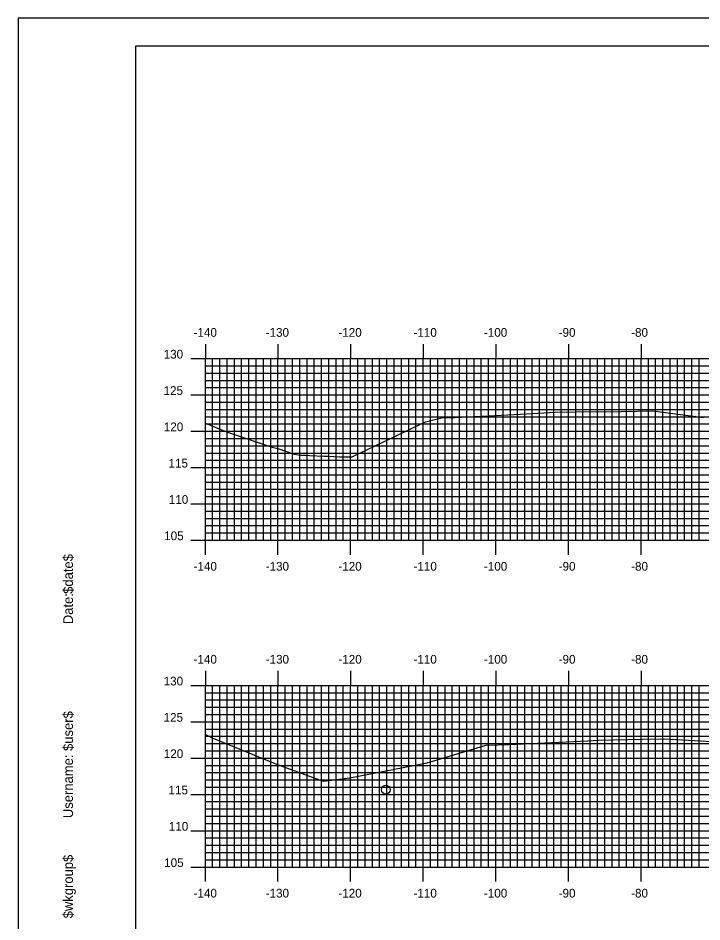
# Model space of a CAD drawing. Extents: x 853894 to 854237, y 366605 to 366825.
# Drawn here: x 853893.7 to 853987.9, y 366700.5 to 366824.9 of the extents above; entities that cross this region are included whole.
import ezdxf

# ---------------------------------------------------------------- set-up
doc = ezdxf.new("R2010")
doc.units = 0
for name, color, linetype in [('BORDER', 7, 'Continuous'), ('H_V ANNOTATION', 7, 'Continuous'), ('M_Roadway_Centerline', 7, 'Continuous'), ('MAJOR', 7, 'Continuous'), ('MINOR', 7, 'Continuous'), ('PLOT BOUNDARY', 7, 'Continuous'), ('S_Drainage_Invert', 7, 'Continuous'), ('S_Roadway_Centerline', 7, 'Continuous')]:
    doc.layers.add(name, color=color, linetype=linetype)

msp = doc.modelspace()

# ---------------------------------------------------------------- linework, layer by layer
at = {"layer": 'BORDER'}
msp.add_lwpolyline([(853909.93, 366611.06), (854229.93, 366611.06), (854229.93, 366821.06), (853909.93, 366821.06)], close=True, dxfattribs=at)
at = {"layer": 'MAJOR'}
for p, q in [((853919.53, 366780.06), (853919.53, 366778.06)), ((853929.53, 366780.06), (853929.53, 366778.06)), ((853939.53, 366780.06), (853939.53, 366778.06)), ((853949.53, 366780.06), (853949.53, 366778.06)), ((853959.53, 366780.06), (853959.53, 366778.06)), ((853969.53, 366780.06), (853969.53, 366778.06)), ((853979.53, 366780.06), (853979.53, 366778.06)), ((853917.53, 366778.06), (853919.53, 366778.06)), ((853919.53, 366778.06), (854199.53, 366778.06)), ((853919.53, 366753.06), (853919.53, 366778.06)), ((853919.53, 366753.06), (853919.53, 366778.06)), ((853919.53, 366778.06), (854199.53, 366778.06)), ((853929.53, 366753.06), (853929.53, 366778.06)), ((853939.53, 366753.06), (853939.53, 366778.06)), ((853949.53, 366753.06), (853949.53, 366778.06)), ((853959.53, 366753.06), (853959.53, 366778.06)), ((853969.53, 366753.06), (853969.53, 366778.06)), ((853979.53, 366753.06), (853979.53, 366778.06)), ((853917.53, 366773.06), (853919.53, 366773.06)), ((853919.53, 366773.06), (854199.53, 366773.06)), ((853917.53, 366768.06), (853919.53, 366768.06)), ((853919.53, 366768.06), (854199.53, 366768.06)), ((853917.53, 366763.06), (853919.53, 366763.06)), ((853919.53, 366763.06), (854199.53, 366763.06)), ((853917.53, 366758.06), (853919.53, 366758.06)), ((853919.53, 366758.06), (854199.53, 366758.06)), ((853917.53, 366753.06), (853919.53, 366753.06)), ((853919.53, 366753.06), (854199.53, 366753.06)), ((853919.53, 366753.06), (854199.53, 366753.06)), ((853919.53, 366751.05), (853919.53, 366753.06)), ((853929.53, 366751.05), (853929.53, 366753.06)), ((853939.53, 366751.05), (853939.53, 366753.06)), ((853949.53, 366751.05), (853949.53, 366753.06)), ((853959.53, 366751.05), (853959.53, 366753.06)), ((853969.53, 366751.05), (853969.53, 366753.06)), ((853979.53, 366751.05), (853979.53, 366753.06)), ((853919.53, 366735.06), (853919.53, 366733.06)), ((853929.53, 366735.06), (853929.53, 366733.06)), ((853939.53, 366735.06), (853939.53, 366733.06)), ((853949.53, 366735.06), (853949.53, 366733.06)), ((853959.53, 366735.06), (853959.53, 366733.06)), ((853969.53, 366735.06), (853969.53, 366733.06)), ((853979.53, 366735.06), (853979.53, 366733.06)), ((853917.53, 366733.06), (853919.53, 366733.06)), ((853919.53, 366733.06), (854199.53, 366733.06)), ((853919.53, 366708.06), (853919.53, 366733.06)), ((853919.53, 366708.06), (853919.53, 366733.06)), ((853919.53, 366733.06), (854199.53, 366733.06)), ((853929.53, 366708.06), (853929.53, 366733.06)), ((853939.53, 366708.06), (853939.53, 366733.06)), ((853949.53, 366708.06), (853949.53, 366733.06)), ((853959.53, 366708.06), (853959.53, 366733.06)), ((853969.53, 366708.06), (853969.53, 366733.06)), ((853979.53, 366708.06), (853979.53, 366733.06)), ((853917.53, 366728.06), (853919.53, 366728.06)), ((853919.53, 366728.06), (854199.53, 366728.06)), ((853917.53, 366723.06), (853919.53, 366723.06)), ((853919.53, 366723.06), (854199.53, 366723.06)), ((853917.53, 366718.06), (853919.53, 366718.06)), ((853919.53, 366718.06), (854199.53, 366718.06)), ((853917.53, 366713.06), (853919.53, 366713.06)), ((853919.53, 366713.06), (854199.53, 366713.06)), ((853917.53, 366708.06), (853919.53, 366708.06)), ((853919.53, 366708.06), (854199.53, 366708.06)), ((853919.53, 366708.06), (854199.53, 366708.06)), ((853919.53, 366706.05), (853919.53, 366708.06)), ((853929.53, 366706.05), (853929.53, 366708.06)), ((853939.53, 366706.05), (853939.53, 366708.06)), ((853949.53, 366706.05), (853949.53, 366708.06)), ((853959.53, 366706.05), (853959.53, 366708.06)), ((853969.53, 366706.05), (853969.53, 366708.06)), ((853979.53, 366706.05), (853979.53, 366708.06))]:
    msp.add_line(p, q, dxfattribs=at)
at = {"layer": 'MINOR'}
for p, q in [((853919.53, 366753.06), (853919.53, 366778.06)), ((853920.53, 366753.06), (853920.53, 366778.06)), ((853921.53, 366753.06), (853921.53, 366778.06)), ((853922.53, 366753.06), (853922.53, 366778.06)), ((853923.53, 366753.06), (853923.53, 366778.06)), ((853924.53, 366753.06), (853924.53, 366778.06)), ((853925.53, 366753.06), (853925.53, 366778.06)), ((853926.53, 366753.06), (853926.53, 366778.06)), ((853927.53, 366753.06), (853927.53, 366778.06)), ((853928.53, 366753.06), (853928.53, 366778.06)), ((853930.53, 366753.06), (853930.53, 366778.06)), ((853931.53, 366753.06), (853931.53, 366778.06)), ((853932.53, 366753.06), (853932.53, 366778.06)), ((853933.53, 366753.06), (853933.53, 366778.06)), ((853934.53, 366753.06), (853934.53, 366778.06)), ((853935.53, 366753.06), (853935.53, 366778.06)), ((853936.53, 366753.06), (853936.53, 366778.06)), ((853937.53, 366753.06), (853937.53, 366778.06)), ((853938.53, 366753.06), (853938.53, 366778.06)), ((853940.53, 366753.06), (853940.53, 366778.06)), ((853941.53, 366753.06), (853941.53, 366778.06)), ((853942.53, 366753.06), (853942.53, 366778.06)), ((853943.53, 366753.06), (853943.53, 366778.06)), ((853944.53, 366753.06), (853944.53, 366778.06)), ((853945.53, 366753.06), (853945.53, 366778.06)), ((853946.53, 366753.06), (853946.53, 366778.06)), ((853947.53, 366753.06), (853947.53, 366778.06)), ((853948.53, 366753.06), (853948.53, 366778.06)), ((853950.53, 366753.06), (853950.53, 366778.06)), ((853951.53, 366753.06), (853951.53, 366778.06)), ((853952.53, 366753.06), (853952.53, 366778.06)), ((853953.53, 366753.06), (853953.53, 366778.06)), ((853954.53, 366753.06), (853954.53, 366778.06)), ((853955.53, 366753.06), (853955.53, 366778.06)), ((853956.53, 366753.06), (853956.53, 366778.06)), ((853957.53, 366753.06), (853957.53, 366778.06)), ((853958.53, 366753.06), (853958.53, 366778.06)), ((853960.53, 366753.06), (853960.53, 366778.06)), ((853961.53, 366753.06), (853961.53, 366778.06)), ((853962.53, 366753.06), (853962.53, 366778.06)), ((853963.53, 366753.06), (853963.53, 366778.06)), ((853964.53, 366753.06), (853964.53, 366778.06)), ((853965.53, 366753.06), (853965.53, 366778.06)), ((853966.53, 366753.06), (853966.53, 366778.06)), ((853967.53, 366753.06), (853967.53, 366778.06)), ((853968.53, 366753.06), (853968.53, 366778.06)), ((853970.53, 366753.06), (853970.53, 366778.06)), ((853971.53, 366753.06), (853971.53, 366778.06)), ((853972.53, 366753.06), (853972.53, 366778.06)), ((853973.53, 366753.06), (853973.53, 366778.06)), ((853974.53, 366753.06), (853974.53, 366778.06)), ((853975.53, 366753.06), (853975.53, 366778.06)), ((853976.53, 366753.06), (853976.53, 366778.06)), ((853977.53, 366753.06), (853977.53, 366778.06)), ((853978.53, 366753.06), (853978.53, 366778.06)), ((853980.53, 366753.06), (853980.53, 366778.06)), ((853981.53, 366753.06), (853981.53, 366778.06)), ((853982.53, 366753.06), (853982.53, 366778.06)), ((853983.53, 366753.06), (853983.53, 366778.06)), ((853984.53, 366753.06), (853984.53, 366778.06)), ((853985.53, 366753.06), (853985.53, 366778.06)), ((853986.53, 366753.06), (853986.53, 366778.06)), ((853987.53, 366753.06), (853987.53, 366778.06)), ((853919.53, 366777.06), (854199.53, 366777.06)), ((853919.53, 366777.06), (853921.53, 366777.06)), ((853919.53, 366776.06), (854199.53, 366776.06)), ((853919.53, 366776.06), (853921.53, 366776.06)), ((853919.53, 366775.06), (854199.53, 366775.06)), ((853919.53, 366775.06), (853921.53, 366775.06)), ((853919.53, 366774.06), (854199.53, 366774.06)), ((853919.53, 366774.06), (853921.53, 366774.06)), ((853919.53, 366772.06), (854199.53, 366772.06)), ((853919.53, 366772.06), (853921.53, 366772.06)), ((853919.53, 366771.06), (854199.53, 366771.06)), ((853919.53, 366771.06), (853921.53, 366771.06)), ((853919.53, 366770.06), (854199.53, 366770.06)), ((853919.53, 366770.06), (853921.53, 366770.06)), ((853919.53, 366769.06), (854199.53, 366769.06)), ((853919.53, 366769.06), (853921.53, 366769.06)), ((853919.53, 366767.06), (854199.53, 366767.06)), ((853919.53, 366767.06), (853921.53, 366767.06)), ((853919.53, 366766.06), (854199.53, 366766.06)), ((853919.53, 366766.06), (853921.53, 366766.06)), ((853919.53, 366765.06), (854199.53, 366765.06)), ((853919.53, 366765.06), (853921.53, 366765.06)), ((853919.53, 366764.06), (854199.53, 366764.06)), ((853919.53, 366764.06), (853921.53, 366764.06)), ((853919.53, 366762.06), (854199.53, 366762.06)), ((853919.53, 366762.06), (853921.53, 366762.06)), ((853919.53, 366761.06), (854199.53, 366761.06)), ((853919.53, 366761.06), (853921.53, 366761.06)), ((853919.53, 366760.06), (854199.53, 366760.06)), ((853919.53, 366760.06), (853921.53, 366760.06)), ((853919.53, 366759.06), (854199.53, 366759.06)), ((853919.53, 366759.06), (853921.53, 366759.06)), ((853919.53, 366757.06), (854199.53, 366757.06)), ((853919.53, 366757.06), (853921.53, 366757.06)), ((853919.53, 366756.06), (854199.53, 366756.06)), ((853919.53, 366756.06), (853921.53, 366756.06)), ((853919.53, 366755.06), (854199.53, 366755.06)), ((853919.53, 366755.06), (853921.53, 366755.06)), ((853919.53, 366754.06), (854199.53, 366754.06)), ((853919.53, 366754.06), (853921.53, 366754.06)), ((853920.53, 366708.06), (853920.53, 366733.06)), ((853921.53, 366708.06), (853921.53, 366733.06)), ((853922.53, 366708.06), (853922.53, 366733.06)), ((853923.53, 366708.06), (853923.53, 366733.06)), ((853924.53, 366708.06), (853924.53, 366733.06)), ((853925.53, 366708.06), (853925.53, 366733.06)), ((853926.53, 366708.06), (853926.53, 366733.06)), ((853927.53, 366708.06), (853927.53, 366733.06)), ((853928.53, 366708.06), (853928.53, 366733.06)), ((853930.53, 366708.06), (853930.53, 366733.06)), ((853931.53, 366708.06), (853931.53, 366733.06)), ((853932.53, 366708.06), (853932.53, 366733.06)), ((853933.53, 366708.06), (853933.53, 366733.06)), ((853934.53, 366708.06), (853934.53, 366733.06)), ((853935.53, 366708.06), (853935.53, 366733.06)), ((853936.53, 366708.06), (853936.53, 366733.06)), ((853937.53, 366708.06), (853937.53, 366733.06)), ((853938.53, 366708.06), (853938.53, 366733.06)), ((853940.53, 366708.06), (853940.53, 366733.06)), ((853941.53, 366708.06), (853941.53, 366733.06)), ((853942.53, 366708.06), (853942.53, 366733.06)), ((853943.53, 366708.06), (853943.53, 366733.06)), ((853944.53, 366708.06), (853944.53, 366733.06)), ((853945.53, 366708.06), (853945.53, 366733.06)), ((853946.53, 366708.06), (853946.53, 366733.06)), ((853947.53, 366708.06), (853947.53, 366733.06)), ((853948.53, 366708.06), (853948.53, 366733.06)), ((853950.53, 366708.06), (853950.53, 366733.06)), ((853951.53, 366708.06), (853951.53, 366733.06)), ((853952.53, 366708.06), (853952.53, 366733.06)), ((853953.53, 366708.06), (853953.53, 366733.06)), ((853954.53, 366708.06), (853954.53, 366733.06)), ((853955.53, 366708.06), (853955.53, 366733.06)), ((853956.53, 366708.06), (853956.53, 366733.06)), ((853957.53, 366708.06), (853957.53, 366733.06)), ((853958.53, 366708.06), (853958.53, 366733.06)), ((853960.53, 366708.06), (853960.53, 366733.06)), ((853961.53, 366708.06), (853961.53, 366733.06)), ((853962.53, 366708.06), (853962.53, 366733.06)), ((853963.53, 366708.06), (853963.53, 366733.06)), ((853964.53, 366708.06), (853964.53, 366733.06)), ((853965.53, 366708.06), (853965.53, 366733.06)), ((853966.53, 366708.06), (853966.53, 366733.06)), ((853967.53, 366708.06), (853967.53, 366733.06)), ((853968.53, 366708.06), (853968.53, 366733.06)), ((853970.53, 366708.06), (853970.53, 366733.06)), ((853971.53, 366708.06), (853971.53, 366733.06)), ((853972.53, 366708.06), (853972.53, 366733.06)), ((853973.53, 366708.06), (853973.53, 366733.06)), ((853974.53, 366708.06), (853974.53, 366733.06)), ((853975.53, 366708.06), (853975.53, 366733.06)), ((853976.53, 366708.06), (853976.53, 366733.06)), ((853977.53, 366708.06), (853977.53, 366733.06)), ((853978.53, 366708.06), (853978.53, 366733.06)), ((853980.53, 366708.06), (853980.53, 366733.06)), ((853981.53, 366708.06), (853981.53, 366733.06)), ((853982.53, 366708.06), (853982.53, 366733.06)), ((853983.53, 366708.06), (853983.53, 366733.06)), ((853984.53, 366708.06), (853984.53, 366733.06)), ((853985.53, 366708.06), (853985.53, 366733.06)), ((853986.53, 366708.06), (853986.53, 366733.06)), ((853987.53, 366708.06), (853987.53, 366733.06)), ((853919.53, 366732.06), (854199.53, 366732.06)), ((853919.53, 366732.06), (853921.53, 366732.06)), ((853919.53, 366731.06), (854199.53, 366731.06)), ((853919.53, 366731.06), (853921.53, 366731.06)), ((853919.53, 366730.06), (854199.53, 366730.06)), ((853919.53, 366730.06), (853921.53, 366730.06)), ((853919.53, 366729.06), (854199.53, 366729.06)), ((853919.53, 366729.06), (853921.53, 366729.06)), ((853919.53, 366727.06), (854199.53, 366727.06)), ((853919.53, 366727.06), (853921.53, 366727.06)), ((853919.53, 366726.06), (854199.53, 366726.06)), ((853919.53, 366726.06), (853921.53, 366726.06)), ((853919.53, 366725.06), (854199.53, 366725.06)), ((853919.53, 366725.06), (853921.53, 366725.06)), ((853919.53, 366724.06), (854199.53, 366724.06)), ((853919.53, 366724.06), (853921.53, 366724.06)), ((853919.53, 366722.06), (854199.53, 366722.06)), ((853919.53, 366722.06), (853921.53, 366722.06)), ((853919.53, 366721.06), (854199.53, 366721.06)), ((853919.53, 366721.06), (853921.53, 366721.06)), ((853919.53, 366720.06), (854199.53, 366720.06)), ((853919.53, 366720.06), (853921.53, 366720.06)), ((853919.53, 366719.06), (854199.53, 366719.06)), ((853919.53, 366719.06), (853921.53, 366719.06)), ((853919.53, 366717.06), (854199.53, 366717.06)), ((853919.53, 366717.06), (853921.53, 366717.06)), ((853919.53, 366716.06), (854199.53, 366716.06)), ((853919.53, 366716.06), (853921.53, 366716.06)), ((853919.53, 366715.06), (854199.53, 366715.06)), ((853919.53, 366715.06), (853921.53, 366715.06)), ((853919.53, 366714.06), (854199.53, 366714.06)), ((853919.53, 366714.06), (853921.53, 366714.06)), ((853919.53, 366712.06), (854199.53, 366712.06)), ((853919.53, 366712.06), (853921.53, 366712.06)), ((853919.53, 366711.06), (854199.53, 366711.06)), ((853919.53, 366711.06), (853921.53, 366711.06)), ((853919.53, 366710.06), (854199.53, 366710.06)), ((853919.53, 366710.06), (853921.53, 366710.06)), ((853919.53, 366709.06), (854199.53, 366709.06)), ((853919.53, 366709.06), (853921.53, 366709.06))]:
    msp.add_line(p, q, dxfattribs=at)
at = {"layer": 'PLOT BOUNDARY'}
msp.add_lwpolyline([(853893.74, 366604.94), (854233.74, 366604.94), (854233.74, 366824.94), (853893.74, 366824.94)], close=True, dxfattribs=at)
at = {"layer": 'S_Drainage_Invert'}
msp.add_circle((853944.38, 366718.71), 0.6, dxfattribs=at)
at = {"layer": 'S_Roadway_Centerline'}
for points in [[(853919.53, 366769.15), (853922.44, 366767.98), (853928.71, 366765.87), (853929.53, 366765.7), (853931.77, 366764.9), (853932.69, 366764.77), (853933.37, 366764.74), (853933.89, 366764.72), (853935.88, 366764.63), (853936.46, 366764.61), (853938.01, 366764.53), (853938.14, 366764.54), (853939.06, 366764.54), (853939.72, 366764.55), (853939.73, 366764.55), (853939.82, 366764.57), (853949.86, 366769.34), (853952.06, 366769.89), (853953.93, 366769.97), (853961.2, 366770.31), (853963.73, 366770.45), (853967.7, 366770.67), (853970.47, 366770.72), (853976.8, 366770.79), (853981.12, 366770.88), (853988.13, 366769.97)], [(853919.53, 366726.3), (853920.49, 366725.85), (853929.32, 366722.21), (853935.75, 366719.89), (853936.19, 366719.93), (853939.43, 366720.32), (853950.09, 366722.4), (853958.33, 366724.88), (853958.44, 366724.82), (853961.33, 366724.93), (853972.18, 366725.43), (853973.68, 366725.54), (853979.73, 366725.67), (853982.75, 366725.72), (853994.26, 366725.08)]]:
    msp.add_lwpolyline(points, dxfattribs=at)

# ---------------------------------------------------------------- texts
at = {"layer": 'BORDER'}
for s, p in [('$date$', (853901.3, 366745.67)), ('Date:', (853901.3, 366741.49)), ('$user$', (853901.3, 366724.04)), ('Username:', (853901.3, 366714.79)), ('$wkgroup$', (853901.3, 366700.99))]:
    msp.add_text(s, height=1.339, rotation=90, dxfattribs=at).set_placement(p)
at = {"layer": 'H_V ANNOTATION'}
for s, p in [('-140', (853917.91, 366781.06)), ('-130', (853927.84, 366781.06)), ('-120', (853937.85, 366781.06)), ('-110', (853948.19, 366781.06)), ('-100', (853957.89, 366781.06)), ('-90', (853968.18, 366781.06)), ('-80', (853978.16, 366781.06)), ('130', (853913.79, 366778.06)), ('125', (853913.78, 366773.06)), ('120', (853913.81, 366768.06)), ('115', (853914.46, 366763.06)), ('110', (853914.5, 366758.06)), ('105', (853913.86, 366753.06)), ('-140', (853917.91, 366748.86)), ('-130', (853927.84, 366748.86)), ('-120', (853937.85, 366748.86)), ('-110', (853948.19, 366748.86)), ('-100', (853957.89, 366748.86)), ('-90', (853968.18, 366748.86)), ('-80', (853978.16, 366748.86)), ('-140', (853917.91, 366736.06)), ('-130', (853927.84, 366736.06)), ('-120', (853937.85, 366736.06)), ('-110', (853948.19, 366736.06)), ('-100', (853957.89, 366736.06)), ('-90', (853968.18, 366736.06)), ('-80', (853978.16, 366736.06)), ('130', (853913.79, 366733.06)), ('125', (853913.78, 366728.06)), ('120', (853913.81, 366723.06)), ('115', (853914.46, 366718.06)), ('110', (853914.5, 366713.06)), ('105', (853913.86, 366708.06)), ('-140', (853917.91, 366703.86)), ('-130', (853927.84, 366703.86)), ('-120', (853937.85, 366703.86)), ('-110', (853948.19, 366703.86)), ('-100', (853957.89, 366703.86)), ('-90', (853968.18, 366703.86)), ('-80', (853978.16, 366703.86))]:
    msp.add_text(s, height=1.2, dxfattribs=at).set_placement(p)
at = {"layer": 'M_Roadway_Centerline'}
for s, p in [('C', (853973.67, 366725.54)), ('L', (853973.68, 366725.53))]:
    msp.add_text(s, height=0.0146, dxfattribs=at).set_placement(p)
at = {"layer": 'MAJOR'}
for p in [(853919.52, 366753.06), (853919.52, 366708.06)]:
    msp.add_text('-', height=0.012, dxfattribs=at).set_placement(p)

doc.saveas('drawing.dxf')
